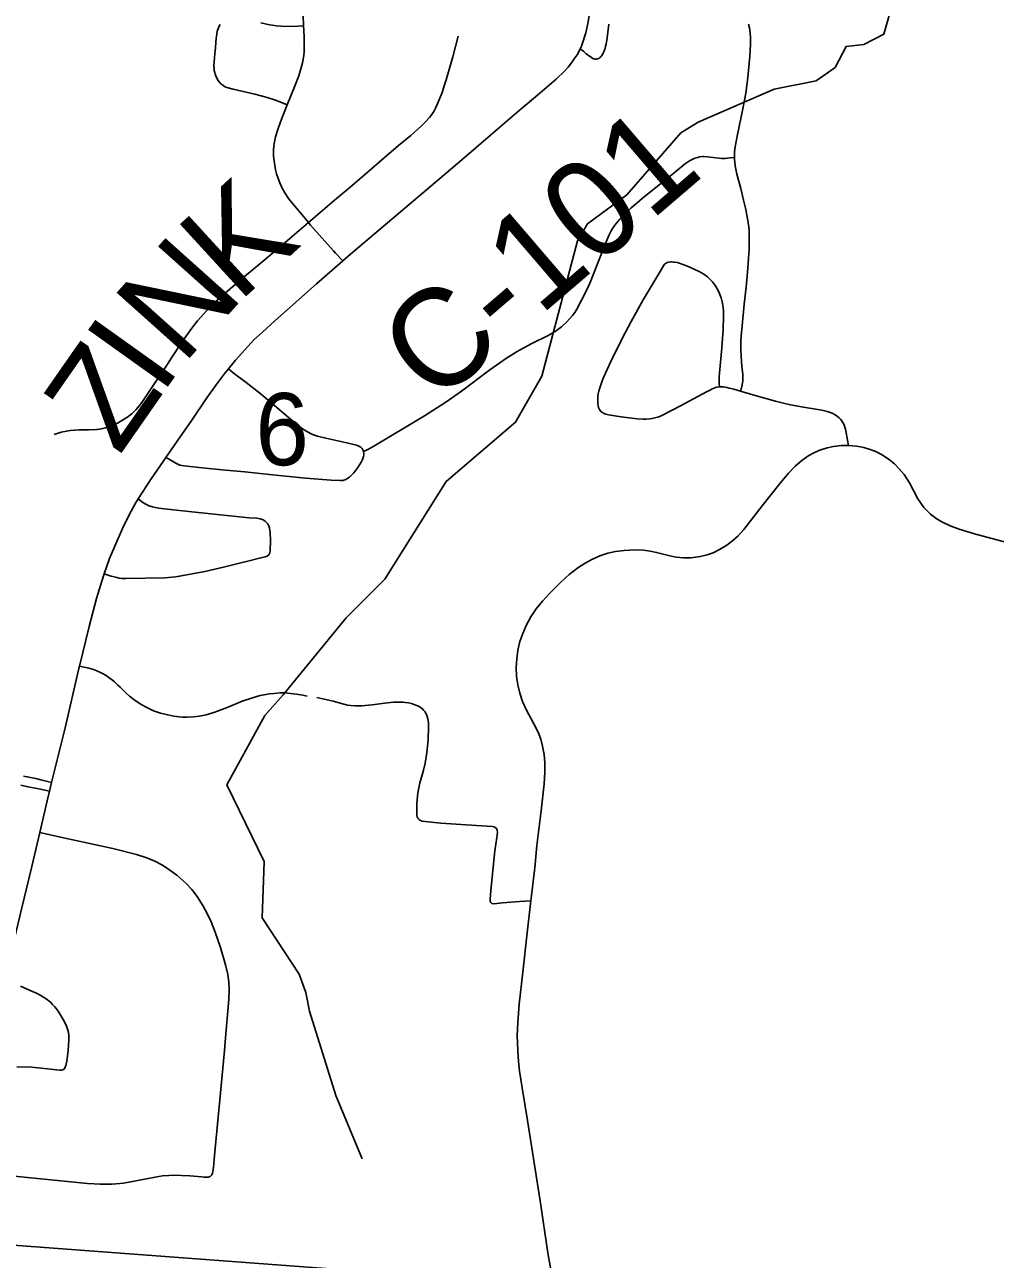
# Model space of a CAD drawing. Extents: x -1.4 to 35.4, y 0 to 22.
# Drawn here: x 25.883 to 26.446, y 14.805 to 15.521 of the extents above; entities that cross this region are included whole.
import ezdxf

# ---------------------------------------------------------------- set-up
doc = ezdxf.new("R2010")
doc.units = 0
for name, color, linetype in [('GM_X_City_Street', 7, 'Continuous'), ('GM_X_County_Road', 7, 'Continuous'), ('GM_X_County_Road_Text', 7, 'Continuous'), ('GM_X_Minor_River', 7, 'Continuous'), ('GM_X_Section_Text', 7, 'Continuous'), ('GM_X_Township_Road', 7, 'Continuous'), ('SC_Scratch1', 7, 'Continuous')]:
    doc.layers.add(name, color=color, linetype=linetype)

msp = doc.modelspace()

# ---------------------------------------------------------------- linework, layer by layer
at = {"layer": 'GM_X_City_Street'}
for points in [[(26.00157, 15.32089), (26.00438, 15.31872), (26.01184, 15.31295), (26.01967, 15.30683), (26.02684, 15.3009), (26.03618, 15.29289), (26.0439, 15.28662), (26.04703, 15.28459), (26.05036, 15.28292), (26.05327, 15.28185), (26.05809, 15.28066), (26.07024, 15.27806), (26.07576, 15.2767), (26.07675, 15.27635), (26.07752, 15.27601), (26.07829, 15.27553), (26.07913, 15.27467), (26.07969, 15.27369), (26.07995, 15.27296)], [(26.29843, 15.308), (26.30558, 15.30593), (26.31876, 15.30225), (26.32662, 15.30033), (26.33398, 15.29892), (26.34458, 15.29717), (26.34649, 15.29678), (26.34883, 15.2962), (26.35055, 15.29564), (26.35175, 15.29516), (26.35303, 15.29452), (26.35398, 15.29395), (26.35487, 15.29329), (26.35575, 15.29255), (26.35654, 15.29172), (26.35716, 15.29095), (26.35791, 15.2898), (26.35841, 15.28886), (26.35889, 15.2877), (26.35937, 15.286), (26.35961, 15.28495), (26.36058, 15.27961), (26.36114, 15.27652)], [(26.07995, 15.27296), (26.08001, 15.27187), (26.07999, 15.27087), (26.0799, 15.2702), (26.07956, 15.26894), (26.07929, 15.26832), (26.07855, 15.26684), (26.07664, 15.2638), (26.07422, 15.26069), (26.0727, 15.25906), (26.07178, 15.25823), (26.07078, 15.25751), (26.06965, 15.25684), (26.06794, 15.25623), (26.06643, 15.25611), (26.06114, 15.2564), (26.04629, 15.25765), (26.02528, 15.25972), (26.01107, 15.26123), (25.99993, 15.26219), (25.98632, 15.26355), (25.97582, 15.26465), (25.97341, 15.26516), (25.97103, 15.26629), (25.96671, 15.26869), (25.96532, 15.26946)], [(26.17696, 15.01252), (26.17712, 15.01401), (26.1792, 15.03152), (26.18048, 15.04445), (26.183, 15.06462), (26.18466, 15.08022), (26.1851, 15.08699), (26.18508, 15.0925), (26.18465, 15.09736), (26.18378, 15.10216), (26.18264, 15.10625), (26.18111, 15.11022), (26.17863, 15.11515), (26.17417, 15.12339), (26.17212, 15.128), (26.17049, 15.13278), (26.16936, 15.13771), (26.16868, 15.14272), (26.16847, 15.14777), (26.16872, 15.15283), (26.16942, 15.15783), (26.17059, 15.16275), (26.17221, 15.16754), (26.17423, 15.17216), (26.17695, 15.17714), (26.18008, 15.18187), (26.1836, 15.18631), (26.18786, 15.19091), (26.19413, 15.19699), (26.19924, 15.2016), (26.20415, 15.20551), (26.20835, 15.20831), (26.21222, 15.21046), (26.21685, 15.21249), (26.22165, 15.21411), (26.22597, 15.2151), (26.231, 15.21568), (26.23727, 15.21594), (26.24232, 15.21576), (26.24609, 15.21529), (26.24981, 15.21454), (26.25762, 15.21247), (26.2612, 15.21176), (26.26542, 15.21136), (26.26966, 15.21143), (26.2751, 15.2121), (26.27924, 15.21307), (26.28264, 15.21432), (26.28643, 15.21621), (26.29058, 15.21878), (26.29401, 15.22132), (26.29715, 15.22418), (26.30041, 15.22781), (26.3111, 15.24149), (26.32069, 15.25375), (26.32631, 15.26046), (26.33024, 15.26453), (26.33405, 15.26785), (26.33821, 15.27077), (26.34098, 15.27232), (26.34447, 15.27388), (26.34872, 15.2752), (26.35245, 15.27599), (26.35688, 15.27648), (26.36114, 15.27652)], [(26.36114, 15.27652), (26.36575, 15.27613), (26.37012, 15.27529), (26.37438, 15.27401), (26.37733, 15.27281), (26.38126, 15.27071), (26.38495, 15.26823), (26.38787, 15.26578), (26.39049, 15.26303), (26.39337, 15.25962), (26.39646, 15.25484), (26.40142, 15.24553), (26.40494, 15.24057), (26.40689, 15.23838), (26.40877, 15.23672), (26.41263, 15.23383), (26.41573, 15.23198), (26.42013, 15.22986), (26.4253, 15.2279), (26.43418, 15.22527), (26.4522, 15.2205)], [(25.92943, 15.20206), (25.9336, 15.20079), (25.93528, 15.20028), (25.93685, 15.19986), (25.9382, 15.19955), (25.93952, 15.1994), (25.94207, 15.19933), (25.96461, 15.19985), (25.97078, 15.20035), (25.97324, 15.20071), (25.98787, 15.20347), (25.99874, 15.206), (26.00955, 15.20867), (26.01197, 15.20923), (26.02041, 15.21127), (26.02282, 15.21189), (26.02395, 15.2124), (26.02491, 15.21319), (26.02555, 15.21424), (26.02576, 15.21544), (26.02591, 15.22147), (26.02569, 15.22614), (26.02536, 15.22856), (26.02504, 15.22991), (26.02443, 15.231), (26.02366, 15.23193), (26.0229, 15.23259), (26.02162, 15.23333), (26.0199, 15.23396), (26.01895, 15.23418), (26.01806, 15.23427), (26.01364, 15.23462), (25.98394, 15.23769), (25.96427, 15.23982), (25.96125, 15.24015), (25.95923, 15.24054), (25.95747, 15.24092), (25.95544, 15.24152), (25.95357, 15.24241), (25.95185, 15.24347), (25.94926, 15.24548)], [(25.91514, 15.14849), (25.91781, 15.14792), (25.92063, 15.14731), (25.92329, 15.14657), (25.92514, 15.1459), (25.92779, 15.14472), (25.92924, 15.14395), (25.93122, 15.14273), (25.93245, 15.14186), (25.9343, 15.1404), (25.93545, 15.1394), (25.93748, 15.13751), (25.93879, 15.13627), (25.94225, 15.13291), (25.94421, 15.13115), (25.94663, 15.12918), (25.94979, 15.12701), (25.95129, 15.12609), (25.95419, 15.12447), (25.95802, 15.12271), (25.9622, 15.12122), (25.96633, 15.12022), (25.96983, 15.11959), (25.97293, 15.11922), (25.97506, 15.11905), (25.97741, 15.11903), (25.98137, 15.11918), (25.98485, 15.11956), (25.98865, 15.12031), (25.99304, 15.1216), (25.99519, 15.12234), (26.00186, 15.12496), (26.00948, 15.1283), (26.01545, 15.13026), (26.01996, 15.13148), (26.02224, 15.13199), (26.02519, 15.13249), (26.02786, 15.13276), (26.03149, 15.13299), (26.03402, 15.13301), (26.03756, 15.13272), (26.04104, 15.13225), (26.04477, 15.13165), (26.04727, 15.13117)], [(26.05276, 15.13033), (26.06052, 15.12865), (26.06222, 15.12821), (26.06838, 15.12642), (26.07069, 15.12593), (26.07256, 15.12567), (26.07507, 15.12543), (26.07877, 15.12544), (26.08494, 15.12604), (26.0923, 15.12708), (26.09723, 15.12757), (26.10064, 15.12765), (26.10282, 15.12761), (26.10406, 15.12751), (26.10588, 15.12726), (26.10775, 15.12683), (26.10958, 15.1262), (26.11177, 15.12526), (26.1128, 15.12466), (26.11359, 15.12414), (26.11426, 15.12354), (26.11472, 15.12305), (26.11539, 15.1222), (26.11582, 15.12155), (26.11633, 15.12058), (26.11681, 15.11943), (26.11723, 15.11791), (26.1174, 15.117), (26.11755, 15.11551), (26.11763, 15.11325), (26.11732, 15.10581), (26.11664, 15.09841), (26.11569, 15.09228), (26.11476, 15.08813), (26.11416, 15.08602), (26.11257, 15.08093), (26.11141, 15.07498), (26.11075, 15.06884), (26.11072, 15.06357), (26.11074, 15.06229), (26.11091, 15.06119), (26.11141, 15.06039), (26.11223, 15.05954), (26.11295, 15.05907), (26.11393, 15.05866), (26.12464, 15.0575), (26.14548, 15.05622), (26.1546, 15.05555), (26.15569, 15.05526), (26.15626, 15.055), (26.15702, 15.05431), (26.15745, 15.05334), (26.1576, 15.05235), (26.15715, 15.04909), (26.15613, 15.04153), (26.1537, 15.01837), (26.15327, 15.01338), (26.15334, 15.01225), (26.15367, 15.01149), (26.15429, 15.01099), (26.1554, 15.01076), (26.16041, 15.01122), (26.1704, 15.012), (26.17696, 15.01252)], [(25.88109, 15.07949), (25.88528, 15.07862), (25.89152, 15.0773), (25.89774, 15.07598)], [(25.88266, 15.08483), (25.88993, 15.0833), (25.8927, 15.08259), (25.89897, 15.08098)], [(25.991, 14.85257), (25.99149, 14.85307), (25.99195, 14.85361), (25.99227, 14.85447), (25.99254, 14.85575), (25.99287, 14.85784), (25.99351, 14.86474), (25.99735, 14.90523), (25.99928, 14.92564), (25.99965, 14.93061), (26.0018, 14.95536), (26.00199, 14.96101), (26.00175, 14.96543), (26.00113, 14.9698), (25.99987, 14.97531), (25.99686, 14.98547), (25.99387, 14.99434), (25.9916, 15.00018), (25.98948, 15.00473), (25.98675, 15.00968), (25.98337, 15.01499), (25.98025, 15.01897), (25.97676, 15.02262), (25.97161, 15.02723), (25.96762, 15.0303), (25.96337, 15.03303), (25.9589, 15.03539), (25.95424, 15.0373), (25.94827, 15.03922), (25.93441, 15.0428), (25.90584, 15.04907), (25.89209, 15.0521)], [(26.20336, 14.71375), (26.20283, 14.71683), (26.20011, 14.73261), (26.19605, 14.75504), (26.19246, 14.77572), (26.19025, 14.78873), (26.18681, 14.80826), (26.18232, 14.83837), (26.17494, 14.885), (26.17186, 14.90402), (26.17044, 14.91364), (26.16978, 14.91925), (26.16929, 14.92568), (26.16908, 14.93443), (26.16929, 14.94193), (26.17011, 14.9525), (26.17223, 14.97104), (26.17489, 14.99387), (26.17696, 15.01252)], [(25.87887, 14.91618), (25.88758, 14.91595), (25.90384, 14.91428), (25.90473, 14.91428), (25.90547, 14.91443), (25.90638, 14.91508), (25.90722, 14.91688), (25.90775, 14.91951), (25.90859, 14.92567), (25.90907, 14.93187), (25.909, 14.93435), (25.90875, 14.93616), (25.90844, 14.93741), (25.90745, 14.94035), (25.90576, 14.94368), (25.90282, 14.94844), (25.90173, 14.94992), (25.90092, 14.95091), (25.89957, 14.95237), (25.89831, 14.95358), (25.8959, 14.95554), (25.89432, 14.95661), (25.89273, 14.95751), (25.89063, 14.95864), (25.88659, 14.96052), (25.88088, 14.96299)], [(25.87348, 14.85312), (25.91988, 14.84853), (25.92727, 14.84809), (25.93084, 14.84806), (25.93403, 14.84817), (25.94075, 14.8488), (25.94683, 14.84979), (25.95906, 14.85219), (25.96329, 14.85288), (25.96702, 14.85318), (25.9698, 14.85329), (25.97425, 14.85324), (25.9791, 14.85296), (25.98593, 14.85231), (25.9873, 14.85221), (25.98897, 14.85213), (25.98978, 14.85213), (25.991, 14.85257)]]:
    msp.add_lwpolyline(points, dxfattribs=at)
at = {"layer": 'GM_X_County_Road'}
for points in [[(26.20551, 15.50661), (26.20624, 15.50812), (26.20725, 15.51094), (26.20805, 15.51344), (26.20875, 15.51584), (26.21004, 15.5212), (26.21154, 15.53035), (26.21224, 15.53676), (26.21264, 15.54188), (26.21304, 15.54693)], [(26.06782, 15.38354), (26.07095, 15.38627), (26.08374, 15.39716), (26.11884, 15.42688), (26.13829, 15.44336), (26.16043, 15.4624), (26.17131, 15.4717), (26.18081, 15.47972), (26.19163, 15.489), (26.19653, 15.49367), (26.19853, 15.49588), (26.2006, 15.49844), (26.20215, 15.50067), (26.20374, 15.50307), (26.20486, 15.50525), (26.20551, 15.50661)], [(26.01637, 15.33787), (26.02128, 15.34225), (26.0285, 15.34884), (26.05267, 15.37034), (26.06782, 15.38354)], [(25.96532, 15.26946), (25.9719, 15.27893), (25.98031, 15.29123), (25.98897, 15.30412), (25.99441, 15.3117), (25.99973, 15.31862), (26.00157, 15.32089), (26.00561, 15.3259), (26.01098, 15.33197), (26.01637, 15.33787)], [(25.94926, 15.24548), (25.95671, 15.25722), (25.96375, 15.2672), (25.96532, 15.26946)], [(25.92943, 15.20206), (25.93261, 15.21089), (25.93677, 15.22085), (25.94096, 15.23007), (25.94521, 15.23851), (25.94769, 15.24298), (25.94926, 15.24548)], [(25.91514, 15.14849), (25.92074, 15.17144), (25.92511, 15.18768), (25.929, 15.20087), (25.92943, 15.20206)], [(25.89774, 15.07598), (25.89897, 15.08098), (25.90679, 15.11275), (25.91484, 15.14725), (25.91514, 15.14849)], [(25.89209, 15.0521), (25.8964, 15.07051), (25.89774, 15.07598)], [(25.87118, 14.9663), (25.87335, 14.97384), (25.87752, 14.99066), (25.88152, 15.00761), (25.88747, 15.03237), (25.89209, 15.0521)]]:
    msp.add_lwpolyline(points, dxfattribs=at)
at = {"layer": 'GM_X_Minor_River'}
msp.add_lwpolyline([(26.38728, 15.53497), (26.38157, 15.51497), (26.37007, 15.50913), (26.3598, 15.50782), (26.35349, 15.4958), (26.34233, 15.48805), (26.31796, 15.48324), (26.27395, 15.46402), (26.26396, 15.45777), (26.23251, 15.42196), (26.20979, 15.40497), (26.20391, 15.39521), (26.18337, 15.31666), (26.16804, 15.29002), (26.12789, 15.25554), (26.09223, 15.19894), (26.06979, 15.17663), (26.03323, 15.13182), (26.02275, 15.11988), (26.0007, 15.07972), (26.02219, 15.03524), (26.02115, 15.00262), (26.0425, 14.96991), (26.04646, 14.9592), (26.04852, 14.94853), (26.06386, 14.89962), (26.07905, 14.86287)], dxfattribs=at)
at = {"layer": 'GM_X_Township_Road'}
for points in [[(26.04512, 15.51978), (26.04504, 15.52167), (26.04458, 15.52966), (26.04435, 15.53336), (26.04424, 15.53706), (26.044, 15.54077), (26.04381, 15.54507), (26.04356, 15.54878), (26.04344, 15.55246), (26.04328, 15.55651), (26.04329, 15.56074)], [(26.03567, 15.47413), (26.03327, 15.47504), (26.02883, 15.47671), (26.024, 15.47832), (26.01975, 15.47955), (26.01677, 15.48031), (26.00423, 15.48311), (26.00052, 15.48418), (25.99935, 15.48476), (25.99821, 15.48554), (25.99722, 15.48633), (25.99626, 15.48732), (25.99549, 15.48838), (25.99473, 15.48966), (25.99425, 15.49075), (25.99385, 15.49196), (25.9936, 15.49288), (25.99335, 15.49395), (25.99321, 15.49504), (25.9931, 15.49649), (25.99318, 15.4989), (25.99356, 15.50355), (25.99396, 15.50712), (25.99424, 15.51028), (25.99448, 15.51273), (25.99477, 15.51513), (25.99509, 15.51669), (25.99533, 15.51769), (25.99576, 15.51879), (25.99619, 15.51964), (25.99683, 15.5207)], [(26.02025, 15.52162), (26.02528, 15.52052), (26.02716, 15.52017), (26.02918, 15.51989), (26.03213, 15.51964), (26.03489, 15.51956), (26.04194, 15.51971), (26.04512, 15.51978)], [(26.03567, 15.47413), (26.04032, 15.48555), (26.0423, 15.49081), (26.044, 15.49622), (26.04451, 15.49833), (26.04491, 15.50053), (26.04526, 15.50276), (26.04543, 15.5049), (26.04552, 15.50867), (26.0455, 15.51302), (26.04524, 15.51736), (26.04512, 15.51978)], [(26.22214, 15.5209), (26.22118, 15.51291), (26.22052, 15.50918), (26.2203, 15.50808), (26.21995, 15.50671), (26.21969, 15.50586), (26.21933, 15.50488), (26.21895, 15.50398), (26.21809, 15.50262), (26.21747, 15.50192), (26.21683, 15.50135), (26.21629, 15.50099), (26.21549, 15.50064), (26.2148, 15.50051), (26.21405, 15.50057), (26.21293, 15.50101), (26.21205, 15.50154), (26.20905, 15.50373), (26.20761, 15.5049), (26.20551, 15.50661)], [(26.29499, 15.44359), (26.29497, 15.44503), (26.29507, 15.44686), (26.2954, 15.44969), (26.29659, 15.45588), (26.29994, 15.47168), (26.30161, 15.4808), (26.30287, 15.48999), (26.30398, 15.50233), (26.30435, 15.50913), (26.3044, 15.51115), (26.30435, 15.51339), (26.30418, 15.51568), (26.30396, 15.51743), (26.30375, 15.51869), (26.30324, 15.52086)], [(26.04793, 15.40578), (26.06418, 15.41976), (26.07083, 15.42523), (26.08021, 15.43321), (26.09185, 15.44328), (26.10024, 15.45042), (26.10738, 15.45636), (26.11339, 15.46161), (26.1159, 15.4642), (26.11811, 15.46669), (26.11944, 15.46841), (26.1206, 15.47018), (26.12171, 15.47222), (26.1232, 15.47552), (26.12549, 15.48114), (26.12695, 15.48571), (26.1278, 15.48861), (26.13164, 15.50195), (26.13323, 15.50793), (26.13476, 15.51382)], [(26.04793, 15.40578), (26.0433, 15.41138), (26.03887, 15.41657), (26.03638, 15.41978), (26.0342, 15.42307), (26.03249, 15.42617), (26.03126, 15.42887), (26.03031, 15.4314), (26.02945, 15.43408), (26.02887, 15.43638), (26.0284, 15.43881), (26.02798, 15.44157), (26.02771, 15.4443), (26.02772, 15.44781), (26.02791, 15.45024), (26.02827, 15.4526), (26.02893, 15.45554), (26.03017, 15.45974), (26.03167, 15.46418), (26.03567, 15.47413)], [(26.07995, 15.27296), (26.08201, 15.27392), (26.08499, 15.27562), (26.11519, 15.29367), (26.12771, 15.30162), (26.1368, 15.30803), (26.15313, 15.32033), (26.16281, 15.32709), (26.16909, 15.33103), (26.17282, 15.33309), (26.17759, 15.33561), (26.18692, 15.34036), (26.1911, 15.3427), (26.1947, 15.34534), (26.1978, 15.34822), (26.20108, 15.35183), (26.20247, 15.3537), (26.20364, 15.35549), (26.20636, 15.36069), (26.20946, 15.36669), (26.21142, 15.37111), (26.21907, 15.39079), (26.22214, 15.39832), (26.22353, 15.40099), (26.22429, 15.40227), (26.22568, 15.40427), (26.22657, 15.40541), (26.22862, 15.40774), (26.23006, 15.40929), (26.23361, 15.41287), (26.23515, 15.41431), (26.23858, 15.4173), (26.24163, 15.41985), (26.25887, 15.43364), (26.26566, 15.43923), (26.26669, 15.43999), (26.26895, 15.44153), (26.26981, 15.44203), (26.27132, 15.44276), (26.27205, 15.44306), (26.2737, 15.4436), (26.27472, 15.44382), (26.27642, 15.44402), (26.27729, 15.44406), (26.27938, 15.444), (26.28604, 15.44307), (26.28752, 15.44295), (26.28859, 15.44292), (26.28971, 15.44301), (26.29236, 15.4433), (26.29499, 15.44359)], [(26.30163, 15.41344), (26.30028, 15.41887), (26.29864, 15.42545), (26.29642, 15.43384), (26.29548, 15.43864), (26.295, 15.44278), (26.29499, 15.44359)], [(26.29843, 15.308), (26.29912, 15.30986), (26.29937, 15.31081), (26.29974, 15.31282), (26.29983, 15.31386), (26.29982, 15.31763), (26.29938, 15.32254), (26.29909, 15.325), (26.29867, 15.3319), (26.29876, 15.33759), (26.29915, 15.34202), (26.29946, 15.34585), (26.30068, 15.35855), (26.30183, 15.36834), (26.30264, 15.37678), (26.30358, 15.39042), (26.30358, 15.39906), (26.3035, 15.40142), (26.30316, 15.4046), (26.30163, 15.41344)], [(25.90049, 15.28285), (25.90274, 15.28364), (25.90451, 15.28416), (25.90758, 15.28485), (25.9099, 15.28525), (25.91255, 15.28548), (25.91505, 15.2856), (25.91873, 15.28556), (25.9205, 15.28553), (25.92516, 15.28573), (25.92683, 15.28597), (25.92872, 15.28634), (25.93276, 15.28755), (25.93717, 15.28953), (25.93917, 15.29066), (25.94256, 15.29274), (25.94544, 15.29486), (25.94691, 15.2962), (25.94802, 15.29738), (25.95071, 15.30065), (25.95178, 15.3021), (25.95483, 15.3066), (25.95743, 15.3108), (25.9606, 15.31531), (25.96162, 15.31681), (25.96425, 15.32079), (25.96624, 15.32373), (25.9685, 15.32725), (25.97489, 15.33693), (25.98022, 15.34449), (25.98198, 15.34687), (25.98363, 15.34882), (25.989, 15.3548), (25.99335, 15.35914), (25.9964, 15.36199), (25.99958, 15.36479), (26.00835, 15.37229), (26.01211, 15.37543), (26.01633, 15.37898), (26.0304, 15.39075), (26.04262, 15.40121), (26.04793, 15.40578)], [(26.06782, 15.38354), (26.06368, 15.38808), (26.06243, 15.38944), (26.04921, 15.40423), (26.04793, 15.40578)], [(26.25382, 15.38063), (26.252, 15.37746), (26.24205, 15.361), (26.23516, 15.34849), (26.22991, 15.33862), (26.22335, 15.32522), (26.2191, 15.31596), (26.21831, 15.31405), (26.21746, 15.31174), (26.21688, 15.30989), (26.21637, 15.30805), (26.21607, 15.30652), (26.21583, 15.30484), (26.21576, 15.30356), (26.21576, 15.30103), (26.21593, 15.29943), (26.21619, 15.29846), (26.21675, 15.29734), (26.21715, 15.29678), (26.21761, 15.29629), (26.21843, 15.29567), (26.21909, 15.29529), (26.21981, 15.29495), (26.22045, 15.29473), (26.22114, 15.29452), (26.22191, 15.29434), (26.22939, 15.29306), (26.23864, 15.29196), (26.24216, 15.29179), (26.24378, 15.29181), (26.2459, 15.29199), (26.24735, 15.29219), (26.24892, 15.29253), (26.25057, 15.29299), (26.25207, 15.29351), (26.25374, 15.29429), (26.26364, 15.29952), (26.2788, 15.30762), (26.28085, 15.30868), (26.28174, 15.30909), (26.28363, 15.30991), (26.28456, 15.31029), (26.28627, 15.31057)], [(26.25382, 15.38063), (26.25454, 15.38162), (26.25534, 15.38225), (26.25604, 15.38258), (26.25678, 15.38278), (26.25788, 15.38293), (26.25857, 15.38296), (26.25965, 15.3829), (26.26028, 15.38283), (26.26189, 15.38255), (26.26304, 15.38224), (26.26774, 15.38057), (26.27453, 15.37749), (26.27722, 15.37593), (26.27933, 15.37434), (26.28015, 15.37361), (26.28158, 15.37219), (26.28225, 15.37142), (26.28352, 15.36978), (26.28422, 15.36873), (26.28502, 15.36738), (26.28576, 15.36595), (26.28655, 15.36414), (26.28727, 15.3621), (26.28795, 15.35979), (26.28848, 15.35673), (26.28862, 15.35421), (26.28866, 15.35171), (26.28843, 15.3437), (26.28779, 15.33317), (26.28633, 15.31837), (26.2862, 15.31652), (26.28613, 15.31436), (26.28617, 15.31239), (26.28627, 15.31057)], [(26.28627, 15.31057), (26.28742, 15.31057), (26.28861, 15.31045), (26.29059, 15.31013), (26.292, 15.30982), (26.29465, 15.30909), (26.29843, 15.308)]]:
    msp.add_lwpolyline(points, dxfattribs=at)
at = {"layer": 'SC_Scratch1'}
for points in [[(26.19002, 14.78927), (25.73939, 14.82301), (25.49604, 14.84707), (25.48524, 14.84739), (25.41955, 14.84933), (25.41754, 14.85053), (25.41561, 14.85132), (25.4129, 14.85206), (25.40985, 14.8525), (25.40393, 14.85327), (25.3804, 14.85554), (25.35566, 14.85782), (25.33746, 14.85954), (25.28767, 14.86423), (25.2469, 14.86843), (25.21338, 14.87134), (25.19896, 14.8731), (25.17599, 14.8761)], [(25.17599, 14.8761), (25.19896, 14.8731), (25.21338, 14.87134), (25.2469, 14.86843), (25.28767, 14.86423), (25.33746, 14.85954), (25.35566, 14.85782), (25.3804, 14.85554), (25.40393, 14.85327), (25.40985, 14.8525), (25.4129, 14.85206), (25.41561, 14.85132), (25.41754, 14.85053), (25.41955, 14.84933), (25.48524, 14.84739), (25.49604, 14.84707), (25.73939, 14.82301), (26.19002, 14.78927)]]:
    msp.add_lwpolyline(points, dxfattribs=at)

# ---------------------------------------------------------------- texts
at = {"layer": 'GM_X_County_Road_Text'}
for s, height, rotation, p in [('C-101', 0.056818, 40.60273, (26.12118, 15.29903)), ('K', 0.05682, 42.4658, (26.00718, 15.35876)), ('N', 0.05682, 48.16604, (25.97488, 15.32257)), ('I', 0.05682, 54.48682, (25.96236, 15.30487)), ('Z', 0.05682, 55.10277, (25.93814, 15.27015))]:
    msp.add_text(s, height=height, rotation=rotation, dxfattribs=at).set_placement(p)
at = {"layer": 'GM_X_Section_Text'}
msp.add_text('6', height=0.04186, rotation=0.00001, dxfattribs=at).set_placement((26.01714, 15.26506))

doc.saveas('drawing.dxf')
